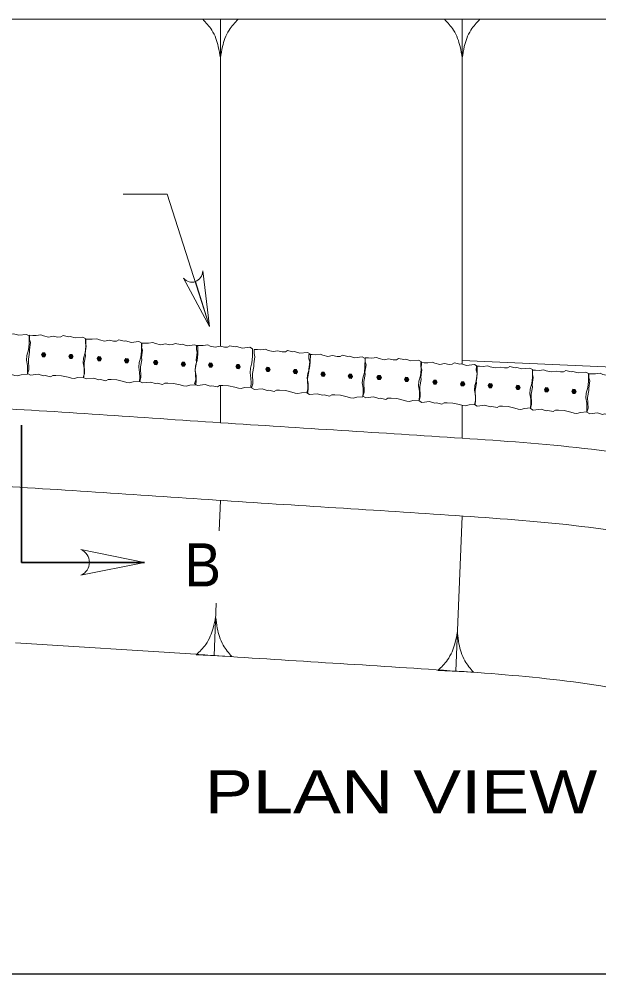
# Model space of a CAD drawing. Extents: x 1043.1 to 1101.1, y 672.4 to 716.4.
# Drawn here: x 1049.41 to 1052.64, y 706.59 to 711.9 of the extents above; entities that cross this region are included whole.
import ezdxf
from ezdxf.enums import TextEntityAlignment as Align

# ---------------------------------------------------------------- set-up
doc = ezdxf.new("R2010")
doc.units = 0
doc.header["$LTSCALE"] = 0.064
doc.layers.add('1', color=7, linetype='Continuous', lineweight=13)

msp = doc.modelspace()

# ---------------------------------------------------------------- hatches: boundary and pattern name
at = {"layer": '1'}
for points in [[(1049.53992, 710.02983), (1049.54542, 710.01783), (1049.5575, 710.01708), (1049.56417, 710.02833), (1049.55875, 710.04008), (1049.5465, 710.04083)], [(1049.69258, 710.0205), (1049.698, 710.00875), (1049.71008, 710.00792), (1049.71675, 710.01908), (1049.71125, 710.031), (1049.69917, 710.03175)], [(1049.85017, 710.00792), (1049.85567, 709.99608), (1049.86767, 709.99525), (1049.87442, 710.00633), (1049.869, 710.01833), (1049.85692, 710.01908)], [(1050.00258, 709.99692), (1050.00792, 709.98492), (1050.02008, 709.98408), (1050.02675, 709.99525), (1050.02133, 710.00708), (1050.00933, 710.00792)], [(1050.16408, 709.98675), (1050.16958, 709.97475), (1050.18167, 709.97408), (1050.18833, 709.98533), (1050.18275, 709.997), (1050.17067, 709.99775)], [(1050.3165, 709.97775), (1050.322, 709.96583), (1050.33425, 709.96508), (1050.34083, 709.97633), (1050.33525, 709.98808), (1050.32325, 709.98892)], [(1050.469, 709.97308), (1050.4745, 709.96108), (1050.48667, 709.96075), (1050.49325, 709.97175), (1050.48767, 709.9835), (1050.47567, 709.98425)], [(1050.6215, 709.96433), (1050.62692, 709.95242), (1050.63908, 709.95175), (1050.64567, 709.96283), (1050.64042, 709.97458), (1050.62808, 709.97533)], [(1050.7885, 709.94908), (1050.79367, 709.93708), (1050.80575, 709.93625), (1050.81275, 709.94708), (1050.80742, 709.95925), (1050.79517, 709.96025)], [(1050.94075, 709.9365), (1050.946, 709.92475), (1050.95808, 709.92358), (1050.96508, 709.9345), (1050.95975, 709.94658), (1050.94758, 709.94775)], [(1051.0945, 709.92183), (1051.09992, 709.90983), (1051.112, 709.90892), (1051.11892, 709.92), (1051.11342, 709.93192), (1051.10125, 709.93275)], [(1051.247, 709.911), (1051.25233, 709.899), (1051.26433, 709.89808), (1051.27108, 709.90925), (1051.26583, 709.92125), (1051.25375, 709.922)], [(1051.40742, 709.904), (1051.41292, 709.892), (1051.42508, 709.89125), (1051.43183, 709.90233), (1051.42642, 709.91408), (1051.41425, 709.91492)], [(1051.56008, 709.89325), (1051.5655, 709.88125), (1051.57758, 709.88042), (1051.58425, 709.8915), (1051.579, 709.90342), (1051.56675, 709.90433)], [(1051.71875, 709.8775), (1051.72425, 709.86575), (1051.73633, 709.865), (1051.74292, 709.87608), (1051.73767, 709.88792), (1051.7255, 709.88875)], [(1051.8715, 709.86833), (1051.87683, 709.85642), (1051.88908, 709.85575), (1051.89567, 709.86675), (1051.89017, 709.87875), (1051.87808, 709.87942)], [(1052.02708, 709.85775), (1052.03258, 709.84583), (1052.04483, 709.84508), (1052.05142, 709.85633), (1052.04592, 709.868), (1052.03383, 709.86875)], [(1052.17983, 709.8485), (1052.18517, 709.8365), (1052.19742, 709.83575), (1052.204, 709.84692), (1052.19867, 709.85883), (1052.18642, 709.8595)], [(1052.33917, 709.83542), (1052.34467, 709.8235), (1052.35675, 709.82283), (1052.36333, 709.83392), (1052.358, 709.84575), (1052.34592, 709.84642)], [(1052.49183, 709.82608), (1052.49725, 709.81408), (1052.5095, 709.8135), (1052.51608, 709.82458), (1052.51058, 709.8365), (1052.4985, 709.83725)]]:
    msp.add_hatch(color=256, dxfattribs=at).paths.add_polyline_path(points)

# ---------------------------------------------------------------- linework, layer by layer
for p, q in [((1047.132, 711.89675), (1056.394, 711.89675)), ((1050.43708, 711.89675), (1050.63492, 711.89675)), ((1050.53608, 710.6015), (1050.53608, 711.89675)), ((1051.78283, 711.89675), (1051.98058, 711.89675)), ((1051.88183, 710.6015), (1051.88183, 711.89675)), ((1050.53608, 710.07625), (1050.53608, 710.6015)), ((1051.88183, 709.97808), (1051.88183, 710.6015)), ((1050.39642, 710.43683), (1050.47508, 710.18642)), ((1051.88183, 709.997), (1053.98258, 709.90708)), ((1050.53608, 709.6515), (1050.53608, 709.85808)), ((1051.88183, 709.56508), (1051.88183, 709.74833)), ((1050.53608, 709.21908), (1050.52908, 709.04933)), ((1051.88183, 709.13233), (1051.84567, 708.26875)), ((1050.5125, 708.648), (1050.50042, 708.35542)), ((1049.39583, 708.42725), (1050.39842, 708.363)), ((1050.59917, 708.3505), (1050.40158, 708.36033)), ((1051.94458, 708.26375), (1051.74683, 708.2735))]:
    msp.add_line(p, q, dxfattribs=at)
at = {"layer": '1', "lineweight": 35}
for q in [(1049.42775, 709.6375), (1050.11308, 708.87442)]:
    msp.add_line((1049.42775, 708.87442), q, dxfattribs=at)
at = {"layer": '1', "lineweight": 25}
msp.add_line((1045.14425, 706.58517), (1075.64425, 706.58517), dxfattribs=at)
at = {"layer": '1'}
for points in [[(1050.47508, 710.18642), (1050.23867, 710.92308), (1049.99425, 710.92308)], [(1050.331, 710.45583), (1050.47508, 710.18642), (1050.43708, 710.49558), (1050.43708, 710.49542)], [(1049.31508, 710.14333), (1049.33233, 710.14383), (1049.34483, 710.151), (1049.37458, 710.1445), (1049.38417, 710.1465), (1049.41275, 710.13783), (1049.45567, 710.14258), (1049.47183, 710.13392)], [(1049.47183, 710.13392), (1049.47092, 710.09), (1049.46775, 710.05608), (1049.459, 710.0255), (1049.457, 709.99933), (1049.46183, 709.96983), (1049.46258, 709.94483), (1049.461, 709.92058)], [(1049.4625, 709.92433), (1049.46917, 709.9465), (1049.4665, 710.00483), (1049.47367, 710.04383), (1049.47233, 710.05692), (1049.47808, 710.09775), (1049.473, 710.1145), (1049.47308, 710.13808)], [(1049.47308, 710.13783), (1049.49092, 710.13733), (1049.5105, 710.13675), (1049.53625, 710.14033), (1049.5505, 710.13433), (1049.57842, 710.12808), (1049.60508, 710.13308), (1049.62967, 710.12825)], [(1049.62967, 710.12825), (1049.64708, 710.12875), (1049.65958, 710.13592), (1049.68925, 710.12942), (1049.69883, 710.13142), (1049.72742, 710.12275), (1049.77025, 710.1275), (1049.7865, 710.11883)], [(1049.7715, 709.9035), (1049.77867, 709.92575), (1049.77658, 709.98408), (1049.78417, 710.02308), (1049.783, 710.03633), (1049.78908, 710.07683), (1049.78417, 710.09392), (1049.78458, 710.11733)], [(1049.7865, 710.11883), (1049.78567, 710.07492), (1049.7825, 710.04108), (1049.77358, 710.01033), (1049.77158, 709.98425), (1049.7765, 709.95475), (1049.77725, 709.92975), (1049.77575, 709.9055)], [(1049.78458, 710.11692), (1049.80225, 710.11633), (1049.822, 710.1155), (1049.84767, 710.11875), (1049.86175, 710.11258), (1049.88967, 710.10592), (1049.91642, 710.1105), (1049.941, 710.1055)], [(1049.941, 710.1055), (1049.95817, 710.10558), (1049.97075, 710.11275), (1050.00058, 710.10575), (1050.01017, 710.10775), (1050.0385, 710.0985), (1050.08158, 710.10292), (1050.09767, 710.09408)], [(1050.09767, 710.09408), (1050.09625, 710.05033), (1050.09275, 710.01633), (1050.08358, 709.98558), (1050.08142, 709.95958), (1050.086, 709.92992), (1050.08633, 709.905), (1050.08458, 709.88092)], [(1050.08675, 709.88108), (1050.09342, 709.90342), (1050.09075, 709.96158), (1050.09792, 710.001), (1050.0965, 710.01408), (1050.10208, 710.05475), (1050.09717, 710.0715), (1050.09725, 710.09492)], [(1050.09717, 710.09458), (1050.11492, 710.09425), (1050.13458, 710.09358), (1050.16025, 710.09725), (1050.1745, 710.09133), (1050.20233, 710.085), (1050.22917, 710.09), (1050.25383, 710.08533)], [(1050.25383, 710.08533), (1050.271, 710.08575), (1050.2835, 710.09292), (1050.31325, 710.08642), (1050.32283, 710.0885), (1050.35133, 710.07983), (1050.39425, 710.08475), (1050.4105, 710.07608)], [(1050.39158, 709.8675), (1050.3985, 709.88992), (1050.39575, 709.94808), (1050.40283, 709.98742), (1050.4015, 710.00042), (1050.407, 710.04133), (1050.40208, 710.058), (1050.40225, 710.08142)], [(1050.4105, 710.07608), (1050.40967, 710.03233), (1050.40642, 709.99833), (1050.39767, 709.96758), (1050.39583, 709.9415), (1050.40075, 709.91192), (1050.4015, 709.88692), (1050.39983, 709.86292)], [(1050.40225, 710.081), (1050.41992, 710.08075), (1050.43942, 710.08025), (1050.46508, 710.08383), (1050.47942, 710.07783), (1050.50725, 710.0715), (1050.53425, 710.07658), (1050.55858, 710.07183)], [(1050.55858, 710.07183), (1050.57575, 710.07242), (1050.58833, 710.07958), (1050.61808, 710.073), (1050.62783, 710.07508), (1050.65633, 710.06633), (1050.69925, 710.07133), (1050.71533, 710.06275)], [(1050.71533, 710.06275), (1050.71467, 710.019), (1050.71142, 709.98492), (1050.70275, 709.95425), (1050.70067, 709.928), (1050.70567, 709.89842), (1050.70658, 709.8735), (1050.705, 709.84933)], [(1050.70917, 709.84558), (1050.71625, 709.8675), (1050.71475, 709.92592), (1050.7225, 709.965), (1050.7215, 709.97808), (1050.72792, 710.01858), (1050.72317, 710.03575), (1050.72383, 710.05892)], [(1050.72367, 710.05858), (1050.74142, 710.05792), (1050.76108, 710.05683), (1050.78683, 710.06), (1050.801, 710.05375), (1050.82867, 710.04675), (1050.8555, 710.05108), (1050.88, 710.04592)], [(1050.88, 710.04592), (1050.89725, 710.04592), (1050.90992, 710.05283), (1050.93958, 710.04558), (1050.94917, 710.04742), (1050.97767, 710.03792), (1051.02058, 710.042), (1051.03667, 710.03292)], [(1051.01617, 709.817), (1051.02317, 709.83925), (1051.021, 709.8975), (1051.0285, 709.93675), (1051.02733, 709.94992), (1051.03325, 709.99042), (1051.02842, 710.0075), (1051.02875, 710.03092)], [(1051.03667, 710.03292), (1051.035, 709.98908), (1051.03117, 709.95508), (1051.02183, 709.92475), (1051.01933, 709.8985), (1051.02358, 709.86892), (1051.024, 709.84383), (1051.02192, 709.81983)], [(1051.02875, 710.0305), (1051.0465, 710.03), (1051.06617, 710.02925), (1051.09192, 710.03242), (1051.106, 710.02633), (1051.13383, 710.01983), (1051.1605, 710.0245), (1051.18508, 710.0195)], [(1051.18508, 710.0195), (1051.20233, 710.01975), (1051.21483, 710.02675), (1051.24458, 710.01992), (1051.25425, 710.02192), (1051.28275, 710.01275), (1051.32575, 710.01725), (1051.34192, 710.00842)], [(1051.34192, 710.00842), (1051.34067, 709.9645), (1051.33708, 709.9305), (1051.32808, 709.89983), (1051.32575, 709.87383), (1051.33033, 709.84408), (1051.331, 709.81925), (1051.32917, 709.79525)], [(1051.32917, 709.7995), (1051.33625, 709.8215), (1051.33408, 709.87983), (1051.34167, 709.919), (1051.34033, 709.93208), (1051.34633, 709.97275), (1051.34142, 709.98975), (1051.34192, 710.01325)], [(1051.34192, 710.01275), (1051.3595, 710.01233), (1051.37925, 710.01142), (1051.405, 710.01483), (1051.41917, 710.0085), (1051.44683, 710.00208), (1051.47367, 710.00692), (1051.49808, 710.00183)], [(1051.49808, 710.00183), (1051.5155, 710.00192), (1051.52808, 710.009), (1051.55775, 710.00225), (1051.56733, 710.00408), (1051.59583, 709.995), (1051.63892, 709.9995), (1051.65492, 709.99075)], [(1051.65492, 709.99075), (1051.65367, 709.94675), (1051.65025, 709.91283), (1051.64108, 709.88225), (1051.63892, 709.856), (1051.64358, 709.82642), (1051.64425, 709.80175), (1051.64233, 709.77742)], [(1051.64142, 709.77242), (1051.64817, 709.79458), (1051.64558, 709.85283), (1051.65275, 709.89192), (1051.6515, 709.905), (1051.65708, 709.94583), (1051.65217, 709.96258), (1051.65242, 709.98608)], [(1051.65217, 709.98558), (1051.67008, 709.98542), (1051.68975, 709.98483), (1051.71517, 709.98842), (1051.7295, 709.98242), (1051.75725, 709.976), (1051.78408, 709.98108), (1051.80875, 709.97608)], [(1051.80875, 709.97608), (1051.82592, 709.97658), (1051.8385, 709.98383), (1051.86825, 709.97725), (1051.878, 709.97908), (1051.9065, 709.97042), (1051.94942, 709.97533), (1051.96558, 709.96675)], [(1051.94975, 709.75258), (1051.9565, 709.77475), (1051.954, 709.83292), (1051.96108, 709.87208), (1051.95983, 709.88525), (1051.96542, 709.92592), (1051.9605, 709.94283), (1051.96067, 709.96625)], [(1051.96558, 709.96675), (1051.9645, 709.92275), (1051.9615, 709.88883), (1051.95267, 709.85792), (1051.95058, 709.83192), (1051.95542, 709.80242), (1051.95617, 709.77742), (1051.95458, 709.75333)], [(1051.9605, 709.96583), (1051.97825, 709.9655), (1051.998, 709.965), (1052.02342, 709.96858), (1052.03775, 709.9625), (1052.06558, 709.95608), (1052.0925, 709.96108), (1052.11717, 709.95633)], [(1052.11717, 709.95633), (1052.13425, 709.95675), (1052.14683, 709.96392), (1052.17667, 709.95733), (1052.18625, 709.95933), (1052.21475, 709.95058), (1052.25758, 709.95542), (1052.27392, 709.94675)], [(1052.27392, 709.94675), (1052.27283, 709.90283), (1052.26967, 709.86892), (1052.26083, 709.838), (1052.25875, 709.812), (1052.26358, 709.7825), (1052.26433, 709.75758), (1052.26292, 709.73342)], [(1052.2725, 709.9435), (1052.29042, 709.94308), (1052.30992, 709.94275), (1052.33558, 709.94633), (1052.34983, 709.94008), (1052.37767, 709.93383), (1052.4045, 709.93883), (1052.42917, 709.934)], [(1049.461, 709.92058), (1049.42675, 709.91833), (1049.40683, 709.91275), (1049.392, 709.91458), (1049.37292, 709.91992), (1049.33617, 709.928), (1049.30458, 709.93008)], [(1049.61933, 709.91492), (1049.602, 709.91458), (1049.58958, 709.90742), (1049.55975, 709.914), (1049.55008, 709.91183), (1049.52142, 709.92075), (1049.4785, 709.91575), (1049.4625, 709.92433)], [(1049.77575, 709.9055), (1049.74142, 709.90325), (1049.72142, 709.8975), (1049.70667, 709.8995), (1049.68758, 709.90475), (1049.65075, 709.91292), (1049.61933, 709.91492)], [(1049.92833, 709.89233), (1049.91108, 709.892), (1049.8985, 709.88508), (1049.86883, 709.892), (1049.85908, 709.89008), (1049.83058, 709.89925), (1049.78758, 709.89483), (1049.7715, 709.9035)], [(1052.26158, 709.73033), (1052.26842, 709.75233), (1052.26592, 709.8105), (1052.273, 709.84983), (1052.27167, 709.86292), (1052.27733, 709.9035), (1052.2725, 709.9205), (1052.27258, 709.94392)], [(1052.42917, 709.934), (1052.44633, 709.93442), (1052.45883, 709.94158), (1052.48867, 709.935), (1052.49833, 709.937), (1052.52692, 709.92833), (1052.56958, 709.93308), (1052.58583, 709.92442)], [(1052.58583, 709.92442), (1052.58492, 709.8805), (1052.58167, 709.8465), (1052.57292, 709.81575), (1052.57092, 709.78983), (1052.57567, 709.76008), (1052.5765, 709.73533), (1052.57492, 709.71108)], [(1052.57608, 709.71033), (1052.58283, 709.7325), (1052.58033, 709.79092), (1052.5875, 709.82992), (1052.58608, 709.84292), (1052.59175, 709.88375), (1052.58692, 709.9005), (1052.587, 709.92408)], [(1052.58692, 709.92358), (1052.60467, 709.92333), (1052.62442, 709.92275), (1052.65008, 709.92633), (1052.66417, 709.92033), (1052.69208, 709.914), (1052.71892, 709.919), (1052.74358, 709.91408)], [(1050.08458, 709.88092), (1050.05008, 709.87883), (1050.03017, 709.8735), (1050.01542, 709.87575), (1049.9965, 709.88108), (1049.95983, 709.88992), (1049.92833, 709.89233)], [(1050.2435, 709.87192), (1050.22633, 709.8715), (1050.21375, 709.86433), (1050.184, 709.871), (1050.17433, 709.86875), (1050.14567, 709.87758), (1050.10275, 709.87258), (1050.08675, 709.88108)], [(1050.39983, 709.86292), (1050.3655, 709.86033), (1050.34567, 709.85483), (1050.33083, 709.85658), (1050.31175, 709.86183), (1050.27517, 709.87008), (1050.2435, 709.87192)], [(1050.54867, 709.85842), (1050.53117, 709.85792), (1050.51892, 709.85075), (1050.48892, 709.8575), (1050.47942, 709.85525), (1050.45075, 709.86425), (1050.40775, 709.85892), (1050.39158, 709.8675)], [(1050.705, 709.84933), (1050.67042, 709.84692), (1050.65058, 709.84133), (1050.63583, 709.84308), (1050.61683, 709.8485), (1050.58, 709.85658), (1050.54867, 709.85842)], [(1050.8655, 709.83258), (1050.84833, 709.83258), (1050.83583, 709.82575), (1050.80608, 709.833), (1050.79642, 709.83108), (1050.768, 709.84075), (1050.72492, 709.8365), (1050.70917, 709.84558)], [(1051.02192, 709.81983), (1050.98725, 709.81808), (1050.96733, 709.81308), (1050.95258, 709.81525), (1050.93375, 709.821), (1050.89725, 709.83), (1050.8655, 709.83258)], [(1051.17275, 709.80625), (1051.1555, 709.80592), (1051.14292, 709.79892), (1051.11342, 709.80592), (1051.10375, 709.80383), (1051.07508, 709.81283), (1051.03217, 709.80833), (1051.01617, 709.817)], [(1051.32917, 709.79525), (1051.29467, 709.79308), (1051.27483, 709.78792), (1051.26008, 709.78983), (1051.24108, 709.79533), (1051.20433, 709.80392), (1051.17275, 709.80625)], [(1051.48592, 709.78858), (1051.46867, 709.78825), (1051.45617, 709.78108), (1051.42642, 709.78825), (1051.41683, 709.78608), (1051.38817, 709.79533), (1051.34533, 709.79075), (1051.32917, 709.7995)], [(1051.64233, 709.77742), (1051.60792, 709.77542), (1051.58783, 709.77008), (1051.57317, 709.77208), (1051.55408, 709.7775), (1051.51742, 709.78625), (1051.48592, 709.78858)], [(1051.79817, 709.76283), (1051.78092, 709.76242), (1051.76842, 709.75525), (1051.73858, 709.76208), (1051.72892, 709.75992), (1051.70033, 709.76883), (1051.6575, 709.76375), (1051.64142, 709.77242)], [(1051.95458, 709.75333), (1051.92025, 709.75092), (1051.90025, 709.74542), (1051.88542, 709.74725), (1051.86642, 709.75258), (1051.82975, 709.76092), (1051.79817, 709.76283)], [(1052.10642, 709.74292), (1052.08925, 709.74258), (1052.07667, 709.73542), (1052.04692, 709.74208), (1052.03717, 709.74), (1052.00858, 709.749), (1051.96592, 709.74392), (1051.94975, 709.75258)], [(1052.26292, 709.73342), (1052.2285, 709.73108), (1052.20858, 709.7255), (1052.19375, 709.72742), (1052.17492, 709.73275), (1052.13817, 709.74108), (1052.10642, 709.74292)], [(1052.4185, 709.7205), (1052.40133, 709.72033), (1052.38883, 709.71308), (1052.35892, 709.71983), (1052.34933, 709.71775), (1052.32075, 709.72675), (1052.27783, 709.72158), (1052.26158, 709.73033)], [(1052.57492, 709.71108), (1052.54067, 709.70883), (1052.52067, 709.70308), (1052.50583, 709.70508), (1052.48683, 709.71033), (1052.45017, 709.71875), (1052.4185, 709.7205)], [(1052.73283, 709.70075), (1052.71575, 709.70042), (1052.70317, 709.69325), (1052.67333, 709.7), (1052.66367, 709.69792), (1052.63508, 709.70675), (1052.59217, 709.70175), (1052.57608, 709.71033)], [(1049.75908, 708.94525), (1050.11308, 708.87442), (1049.75908, 708.80367), (1049.75917, 708.80375)]]:
    msp.add_lwpolyline(points, dxfattribs=at)
for points in [[(1049.53992, 710.02983), (1049.54542, 710.01783), (1049.5575, 710.01708), (1049.56417, 710.02833), (1049.55875, 710.04008), (1049.5465, 710.04083)], [(1049.69258, 710.0205), (1049.698, 710.00875), (1049.71008, 710.00792), (1049.71675, 710.01908), (1049.71125, 710.031), (1049.69917, 710.03175)], [(1049.85017, 710.00792), (1049.85567, 709.99608), (1049.86767, 709.99525), (1049.87442, 710.00633), (1049.869, 710.01833), (1049.85692, 710.01908)], [(1050.00258, 709.99692), (1050.00792, 709.98492), (1050.02008, 709.98408), (1050.02675, 709.99525), (1050.02133, 710.00708), (1050.00933, 710.00792)], [(1050.16408, 709.98675), (1050.16958, 709.97475), (1050.18167, 709.97408), (1050.18833, 709.98533), (1050.18275, 709.997), (1050.17067, 709.99775)], [(1050.3165, 709.97775), (1050.322, 709.96583), (1050.33425, 709.96508), (1050.34083, 709.97633), (1050.33525, 709.98808), (1050.32325, 709.98892)], [(1050.469, 709.97308), (1050.4745, 709.96108), (1050.48667, 709.96075), (1050.49325, 709.97175), (1050.48767, 709.9835), (1050.47567, 709.98425)], [(1050.6215, 709.96433), (1050.62692, 709.95242), (1050.63908, 709.95175), (1050.64567, 709.96283), (1050.64042, 709.97458), (1050.62808, 709.97533)], [(1050.7885, 709.94908), (1050.79367, 709.93708), (1050.80575, 709.93625), (1050.81275, 709.94708), (1050.80742, 709.95925), (1050.79517, 709.96025)], [(1050.94075, 709.9365), (1050.946, 709.92475), (1050.95808, 709.92358), (1050.96508, 709.9345), (1050.95975, 709.94658), (1050.94758, 709.94775)], [(1051.0945, 709.92183), (1051.09992, 709.90983), (1051.112, 709.90892), (1051.11892, 709.92), (1051.11342, 709.93192), (1051.10125, 709.93275)], [(1051.247, 709.911), (1051.25233, 709.899), (1051.26433, 709.89808), (1051.27108, 709.90925), (1051.26583, 709.92125), (1051.25375, 709.922)], [(1051.40742, 709.904), (1051.41292, 709.892), (1051.42508, 709.89125), (1051.43183, 709.90233), (1051.42642, 709.91408), (1051.41425, 709.91492)], [(1051.56008, 709.89325), (1051.5655, 709.88125), (1051.57758, 709.88042), (1051.58425, 709.8915), (1051.579, 709.90342), (1051.56675, 709.90433)], [(1051.71875, 709.8775), (1051.72425, 709.86575), (1051.73633, 709.865), (1051.74292, 709.87608), (1051.73767, 709.88792), (1051.7255, 709.88875)], [(1051.8715, 709.86833), (1051.87683, 709.85642), (1051.88908, 709.85575), (1051.89567, 709.86675), (1051.89017, 709.87875), (1051.87808, 709.87942)], [(1052.02708, 709.85775), (1052.03258, 709.84583), (1052.04483, 709.84508), (1052.05142, 709.85633), (1052.04592, 709.868), (1052.03383, 709.86875)], [(1052.17983, 709.8485), (1052.18517, 709.8365), (1052.19742, 709.83575), (1052.204, 709.84692), (1052.19867, 709.85883), (1052.18642, 709.8595)], [(1052.33917, 709.83542), (1052.34467, 709.8235), (1052.35675, 709.82283), (1052.36333, 709.83392), (1052.358, 709.84575), (1052.34592, 709.84642)], [(1052.49183, 709.82608), (1052.49725, 709.81408), (1052.5095, 709.8135), (1052.51608, 709.82458), (1052.51058, 709.8365), (1052.4985, 709.83725)]]:
    msp.add_lwpolyline(points, close=True, dxfattribs=at)
msp.add_arc((1049.73046, 708.87452), 0.0764, 292.08605, 67.91218, dxfattribs=at)
msp.add_ellipse((1050.37673, 710.49908), major_axis=(0, -0.06601), ratio=0.916667, start_param=5.4282542, end_param=7.7988673, dxfattribs=at)
for points in [[(1050.53608, 711.68092), (1050.52417, 711.74358), (1050.51075, 711.78875), (1050.4875, 711.836), (1050.43708, 711.89675)], [(1050.63492, 711.89675), (1050.5845, 711.836), (1050.56125, 711.78875), (1050.548, 711.74358), (1050.53608, 711.68092)], [(1051.88183, 711.68092), (1051.86992, 711.74358), (1051.8565, 711.78875), (1051.83317, 711.836), (1051.78283, 711.89675)], [(1051.98058, 711.89675), (1051.93033, 711.836), (1051.907, 711.78875), (1051.89367, 711.74358), (1051.88183, 711.68092)], [(1047.132, 709.91058), (1047.84433, 709.82425), (1049.19017, 709.73792), (1050.53608, 709.6515), (1051.88183, 709.56508), (1053.22758, 709.39258), (1053.76308, 709.23083)], [(1047.08833, 709.4815), (1047.81092, 709.394), (1049.167, 709.30692), (1050.51275, 709.22058), (1051.84692, 709.13492), (1053.14792, 708.968), (1053.9465, 708.70742)], [(1050.40158, 708.36033), (1050.45433, 708.41842), (1050.47967, 708.46458), (1050.49492, 708.50892), (1050.50933, 708.57108)], [(1050.50933, 708.57108), (1050.5185, 708.50783), (1050.53, 708.46208), (1050.55142, 708.41358), (1050.59917, 708.3505)], [(1051.74683, 708.2735), (1051.79975, 708.33142), (1051.82508, 708.37775), (1051.84017, 708.42208), (1051.85475, 708.48425)], [(1051.85475, 708.48425), (1051.86392, 708.42092), (1051.87542, 708.37533), (1051.89675, 708.32658), (1051.94458, 708.26375)], [(1050.39842, 708.363), (1050.46633, 708.35842), (1051.77733, 708.2745), (1052.989, 708.11892), (1053.73617, 707.87458)]]:
    msp.add_spline(points, degree=3, dxfattribs=at)

# ---------------------------------------------------------------- texts
for s, width, p in [('B', 0.95, (1050.4375, 708.74033)), ('PLAN VIEW', 1.25, (1051.54142, 707.4785))]:
    msp.add_text(s, height=0.24, dxfattribs=dict(at, width=width)).set_placement(p, align=Align.CENTER)

doc.saveas('drawing.dxf')
